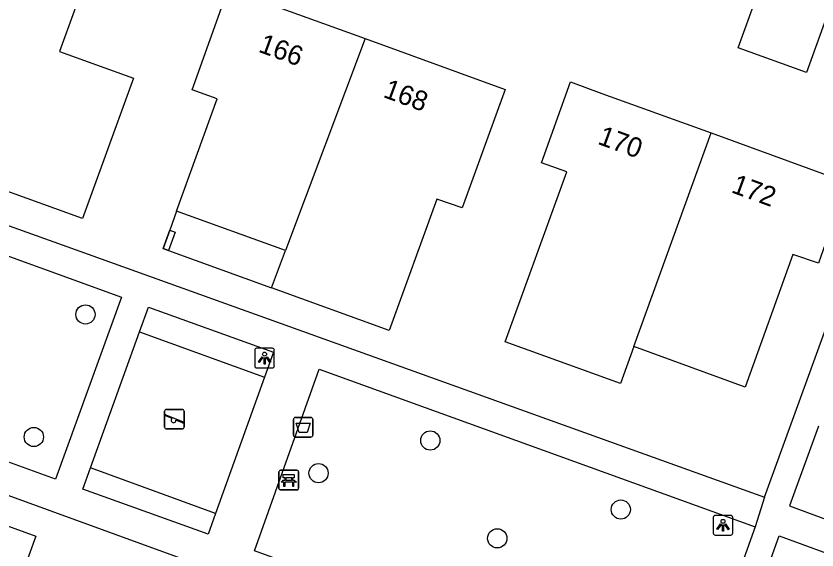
# Model space of a CAD drawing. Extents: x 155275 to 156263, y 382654 to 383635.
# Drawn here: x 155842.67 to 155883.46, y 382948.94 to 382976.11 of the extents above; entities that cross this region are included whole.
import ezdxf

# ---------------------------------------------------------------- set-up
doc = ezdxf.new("R2010")
doc.units = 0
for name, color, linetype in [('IMGEO_Afvalbak', 7, 'Continuous'), ('IMGEO_Bank', 7, 'Continuous'), ('IMGEO_Boom', 7, 'Continuous'), ('IMGEO_Groenvoorziening', 7, 'Continuous'), ('IMGEO_Lichtpunt', 7, 'Continuous'), ('IMGEO_Pand', 7, 'Continuous'), ('IMGEO_Pand_nummerreeks', 7, 'Continuous'), ('IMGEO_Pand_overbouw', 7, 'Continuous'), ('IMGEO_Speelvoorziening', 7, 'Continuous'), ('IMGEO_Voetpad_open', 7, 'Continuous')]:
    doc.layers.add(name, color=color, linetype=linetype)

msp = doc.modelspace()

# ---------------------------------------------------------------- linework, layer by layer
at = {"layer": 'IMGEO_Afvalbak'}
for p, q in [((155856.796, 382954.778), (155856.796, 382955.578)), ((155856.796, 382955.578), (155856.796, 382954.778)), ((155856.896, 382955.678), (155857.686, 382955.678)), ((155857.686, 382955.678), (155856.896, 382955.678)), ((155857.786, 382955.578), (155857.786, 382954.778)), ((155857.786, 382954.778), (155857.786, 382955.578)), ((155857.686, 382954.678), (155856.896, 382954.678)), ((155856.896, 382954.678), (155857.686, 382954.678))]:
    msp.add_line(p, q, dxfattribs=at)
msp.add_lwpolyline([(155856.939, 382955.392), (155857.643, 382955.392), (155857.494, 382954.922), (155857.088, 382954.922), (155856.939, 382955.392)], dxfattribs=at)
for centre, start, end in [((155856.896, 382955.578), 90, 180), ((155856.896, 382955.578), 90, 180), ((155857.686, 382955.578), 0, 90), ((155857.686, 382955.578), 360, 90), ((155856.896, 382954.778), 180, 270), ((155856.896, 382954.778), 180, 270), ((155857.686, 382954.778), 270, 0), ((155857.686, 382954.778), 270, 0)]:
    msp.add_arc(centre, 0.1, start, end, dxfattribs=at)
at = {"layer": 'IMGEO_Bank'}
for p, q in [((155856.06, 382952.065), (155856.06, 382952.906)), ((155856.06, 382952.906), (155856.06, 382952.065)), ((155856.135, 382952.99), (155856.976, 382952.99)), ((155856.976, 382952.99), (155856.135, 382952.99)), ((155857.06, 382952.915), (155857.06, 382952.074)), ((155857.06, 382952.074), (155857.06, 382952.915)), ((155856.369, 382952.496), (155856.369, 382952.602)), ((155856.413, 382952.602), (155856.413, 382952.496)), ((155856.701, 382952.608), (155856.419, 382952.608)), ((155856.419, 382952.49), (155856.701, 382952.49)), ((155856.707, 382952.496), (155856.707, 382952.602)), ((155856.751, 382952.602), (155856.751, 382952.496)), ((155856.757, 382952.388), (155856.364, 382952.388)), ((155856.985, 382951.99), (155856.144, 382951.99)), ((155856.144, 382951.99), (155856.985, 382951.99))]:
    msp.add_line(p, q, dxfattribs=at)
for points in [[(155856.307, 382952.388), (155856.165, 382952.388), (155856.277, 382952.49), (155856.363, 382952.49)], [(155856.363, 382952.608), (155856.277, 382952.608), (155856.277, 382952.769), (155856.84, 382952.769), (155856.84, 382952.608), (155856.757, 382952.608)], [(155856.757, 382952.49), (155856.84, 382952.49), (155856.952, 382952.388), (155856.813, 382952.388)], [(155856.357, 382952.381), (155856.357, 382952.174), (155856.314, 382952.174), (155856.314, 382952.381)], [(155856.807, 382952.381), (155856.807, 382952.174), (155856.763, 382952.174), (155856.763, 382952.381)]]:
    msp.add_lwpolyline(points, dxfattribs=at)
for centre, radius, start, end in [((155856.138, 382952.912), 0.0779, 92.4484, 184.2845), ((155856.138, 382952.912), 0.0779, 92.4484, 184.2845), ((155856.982, 382952.912), 0.0779, 2.4484, 94.2845), ((155856.982, 382952.912), 0.0779, 2.4484, 94.2845), ((155856.362, 382952.601), 0.00671, 2.8957, 87.1043), ((155856.362, 382952.497), 0.00671, 272.8957, 357.1043), ((155856.419, 382952.601), 0.00671, 92.8957, 177.1043), ((155856.419, 382952.497), 0.00671, 182.8957, 267.1043), ((155856.701, 382952.601), 0.00671, 2.8957, 87.1043), ((155856.701, 382952.497), 0.00671, 272.8957, 357.1043), ((155856.758, 382952.601), 0.00671, 92.8957, 177.1043), ((155856.758, 382952.497), 0.00671, 182.8957, 267.1043), ((155856.138, 382952.068), 0.0779, 182.4484, 274.2845), ((155856.138, 382952.068), 0.0779, 182.4484, 274.2845), ((155856.307, 382952.381), 0.00671, 2.8957, 87.1043), ((155856.364, 382952.381), 0.00671, 92.8957, 177.1043), ((155856.756, 382952.381), 0.00671, 2.8957, 87.1043), ((155856.813, 382952.381), 0.00671, 92.8957, 177.1043), ((155856.982, 382952.068), 0.0779, 272.4484, 4.2845), ((155856.982, 382952.068), 0.0779, 272.4484, 4.2845)]:
    msp.add_arc(centre, radius, start, end, dxfattribs=at)
at = {"layer": 'IMGEO_Boom'}
for centre in [(155846.202, 382960.925), (155843.573, 382954.686), (155863.767, 382954.507), (155858.076, 382952.845), (155873.472, 382950.993), (155867.179, 382949.526)]:
    msp.add_circle(centre, 0.489, dxfattribs=at)
at = {"layer": 'IMGEO_Groenvoorziening'}
for points in [[(155848.959, 382960.042), (155855.326, 382957.731)], [(155852.833, 382950.787), (155846.455, 382953.112)]]:
    msp.add_lwpolyline(points, dxfattribs=at)
at = {"layer": 'IMGEO_Lichtpunt'}
for p, q in [((155854.827, 382959.106), (155854.827, 382958.299)), ((155854.827, 382959.106), (155854.827, 382958.299)), ((155855.729, 382959.201), (155854.921, 382959.201)), ((155855.729, 382959.201), (155854.921, 382959.201)), ((155855.823, 382958.299), (155855.823, 382959.106)), ((155855.823, 382958.299), (155855.823, 382959.106)), ((155854.921, 382958.205), (155855.729, 382958.205)), ((155854.921, 382958.205), (155855.729, 382958.205)), ((155878.18, 382950.595), (155878.18, 382949.788)), ((155878.18, 382950.595), (155878.18, 382949.788)), ((155879.082, 382950.69), (155878.274, 382950.69)), ((155879.082, 382950.69), (155878.274, 382950.69)), ((155879.176, 382949.788), (155879.176, 382950.595)), ((155879.176, 382949.788), (155879.176, 382950.595)), ((155878.274, 382949.694), (155879.082, 382949.694)), ((155878.274, 382949.694), (155879.082, 382949.694))]:
    msp.add_line(p, q, dxfattribs=at)
for points in [[(155855.201, 382958.77), (155855.24, 382958.742), (155855.052, 382958.48), (155855.014, 382958.507), (155855.201, 382958.77)], [(155855.303, 382958.722), (155855.35, 382958.722), (155855.35, 382958.4), (155855.303, 382958.4), (155855.303, 382958.722)], [(155855.413, 382958.742), (155855.451, 382958.769), (155855.638, 382958.507), (155855.599, 382958.479), (155855.413, 382958.742)], [(155878.554, 382950.259), (155878.593, 382950.231), (155878.405, 382949.969), (155878.367, 382949.996), (155878.554, 382950.259)], [(155878.656, 382950.211), (155878.703, 382950.211), (155878.703, 382949.889), (155878.656, 382949.889), (155878.656, 382950.211)], [(155878.766, 382950.231), (155878.804, 382950.258), (155878.991, 382949.996), (155878.952, 382949.968), (155878.766, 382950.231)]]:
    msp.add_lwpolyline(points, dxfattribs=at)
for centre in [(155855.326, 382958.904), (155878.679, 382950.393)]:
    msp.add_circle(centre, 0.0994, dxfattribs=at)
for centre, start, end in [((155854.921, 382959.106), 90, 180), ((155854.921, 382959.106), 90, 180), ((155855.729, 382959.106), 0, 90), ((155855.729, 382959.106), 0, 90), ((155854.921, 382958.299), 180, 270), ((155854.921, 382958.299), 180, 270), ((155855.729, 382958.299), 270, 0), ((155855.729, 382958.299), 270, 360), ((155878.274, 382950.595), 90, 180), ((155878.274, 382950.595), 90, 180), ((155879.082, 382950.595), 0, 90), ((155879.082, 382950.595), 0, 90), ((155878.274, 382949.788), 180, 270), ((155878.274, 382949.788), 180, 270), ((155879.082, 382949.788), 270, 0), ((155879.082, 382949.788), 270, 360)]:
    msp.add_arc(centre, 0.0946, start, end, dxfattribs=at)
at = {"layer": 'IMGEO_Pand'}
for points in [[(155847.501, 382991.829), (155850.461, 382990.758), (155848.665, 382985.778), (155852.768, 382984.295), (155850.381, 382977.751), (155846.624, 382979.121), (155844.881, 382974.314), (155848.641, 382972.949), (155846.046, 382965.802), (155838.99, 382968.361)], [(155881.26, 382979.539), (155884.744, 382978.29), (155882.935, 382973.245), (155879.452, 382974.493), (155880.383, 382977.091)], [(155856.389, 382964.171), (155850.842, 382966.173), (155852.91, 382971.892), (155851.641, 382972.351), (155853.474, 382977.5), (155859.184, 382975.435), (155860.453, 382974.972)], [(155860.453, 382974.972), (155867.583, 382972.373), (155865.394, 382966.345), (155864.103, 382966.792), (155861.667, 382960.114), (155855.679, 382962.284), (155856.389, 382964.171)], [(155860.453, 382974.972), (155856.389, 382964.171)], [(155874.134, 382959.286), (155873.452, 382957.401), (155867.58, 382959.534), (155870.721, 382968.181), (155869.429, 382968.643), (155870.913, 382972.76), (155872.512, 382972.176), (155878.069, 382970.162)], [(155878.069, 382970.162), (155885.011, 382967.646), (155883.894, 382964.553), (155883.534, 382963.532), (155882.242, 382963.972), (155879.802, 382957.216), (155874.134, 382959.286)], [(155874.134, 382959.286), (155878.069, 382970.162)], [(155850.494, 382965.215), (155850.779, 382965.118), (155850.439, 382964.178), (155850.159, 382964.279), (155850.494, 382965.215)], [(155839.05, 382924.691), (155835.511, 382925.998), (155837.817, 382932.357), (155835.614, 382933.153), (155838.111, 382940.031), (155833.823, 382941.592), (155837.55, 382951.859), (155843.674, 382949.631), (155842.963, 382947.676), (155842.724, 382947.018), (155845.261, 382946.095), (155843.597, 382941.639), (155842.987, 382941.864), (155842.064, 382939.359), (155842.674, 382939.134), (155839.795, 382931.32), (155841.21, 382930.822), (155841.044, 382930.35)]]:
    msp.add_lwpolyline(points, dxfattribs=at)
at = {"layer": 'IMGEO_Pand_overbouw'}
msp.add_lwpolyline([(155856.389, 382964.171), (155850.842, 382966.173), (155850.494, 382965.215), (155850.159, 382964.279), (155850.439, 382964.178), (155855.679, 382962.284)], close=True, dxfattribs=at)
at = {"layer": 'IMGEO_Speelvoorziening'}
for p, q in [((155850.232, 382955.193), (155850.232, 382955.993)), ((155850.232, 382955.993), (155850.232, 382955.193)), ((155850.615, 382955.621), (155850.276, 382955.758)), ((155850.301, 382955.818), (155851.177, 382955.465)), ((155850.332, 382956.093), (155851.122, 382956.093)), ((155851.122, 382956.093), (155850.332, 382956.093)), ((155851.222, 382955.993), (155851.222, 382955.193)), ((155851.222, 382955.193), (155851.222, 382955.993)), ((155851.153, 382955.405), (155850.813, 382955.542)), ((155851.122, 382955.093), (155850.332, 382955.093)), ((155850.332, 382955.093), (155851.122, 382955.093))]:
    msp.add_line(p, q, dxfattribs=at)
for centre, radius, start, end in [((155850.332, 382955.993), 0.1, 90, 180), ((155850.332, 382955.993), 0.1, 90, 180), ((155850.289, 382955.788), 0.0327, 68.078, 248.078), ((155851.122, 382955.993), 0.1, 0, 90), ((155851.122, 382955.993), 0.1, 360, 90), ((155850.694, 382955.531), 0.12, 130.9928, 5.1632), ((155851.165, 382955.435), 0.0327, 248.078, 68.078), ((155850.332, 382955.193), 0.1, 180, 270), ((155850.332, 382955.193), 0.1, 180, 270), ((155851.122, 382955.193), 0.1, 270, 0), ((155851.122, 382955.193), 0.1, 270, 0)]:
    msp.add_arc(centre, radius, start, end, dxfattribs=at)
at = {"layer": 'IMGEO_Voetpad_open'}
for points in [[(155794.244, 382982.888), (155817.258, 382974.414), (155845.91, 382964.137), (155880.792, 382951.626)], [(155880.792, 382951.626), (155889.819, 382976.447), (155889.87, 382976.588)], [(155814.373, 382974.023), (155848.041, 382961.804), (155844.676, 382952.537), (155811.038, 382964.752), (155814.373, 382974.023)], [(155876.306, 382939.329), (155819.213, 382960.092), (155789.359, 382971.074)], [(155848.959, 382960.042), (155849.415, 382961.302), (155855.781, 382958.999), (155855.326, 382957.731)], [(155846.455, 382953.112), (155848.959, 382960.042)], [(155876.986, 382940.814), (155854.818, 382948.899), (155858.099, 382958.145), (155880.309, 382950.108)], [(155855.326, 382957.731), (155852.833, 382950.787)], [(155883.547, 382955.236), (155882.057, 382951.18), (155885.787, 382949.804), (155886.132, 382949.679)], [(155852.833, 382950.787), (155852.46, 382949.747), (155846.065, 382952.033), (155846.455, 382953.112)], [(155880.792, 382951.626), (155880.309, 382950.108)], [(155880.309, 382950.108), (155876.986, 382940.814)], [(155882.984, 382938.626), (155878.197, 382940.349), (155878.58, 382941.412), (155881.532, 382949.659), (155886.356, 382947.885)]]:
    msp.add_lwpolyline(points, dxfattribs=at)

# ---------------------------------------------------------------- texts
at = {"layer": 'IMGEO_Pand_nummerreeks'}
for s, rotation, p in [('166', 339.9178, (155854.964, 382974.307)), ('168', 339.7746, (155861.319, 382972.001)), ('170', 339.8777, (155872.246, 382969.618)), ('172', 339.8777, (155879.05, 382967.152))]:
    msp.add_text(s, height=1, rotation=rotation, dxfattribs=at).set_placement(p)

doc.saveas('drawing.dxf')
